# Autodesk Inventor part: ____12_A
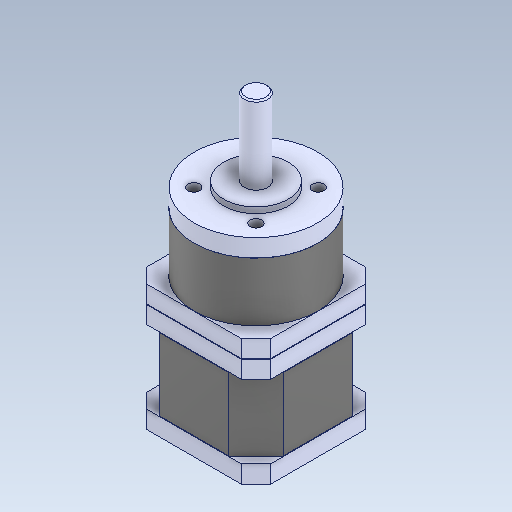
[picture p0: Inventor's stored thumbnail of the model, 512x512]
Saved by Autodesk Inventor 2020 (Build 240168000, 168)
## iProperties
Created: 2017-09
Part Number: ____12_A
Material: Générique
Document SubType Name: Modeling
Designer: bruno
Density: 1 g/cm^3
Appearance: Par défaut
Author: bruno
Sending System: SolidWorks 2016
Last Author: Prof
Last Saved: 2018-10-03
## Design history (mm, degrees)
feature "Importée1"
node "Solide1"
